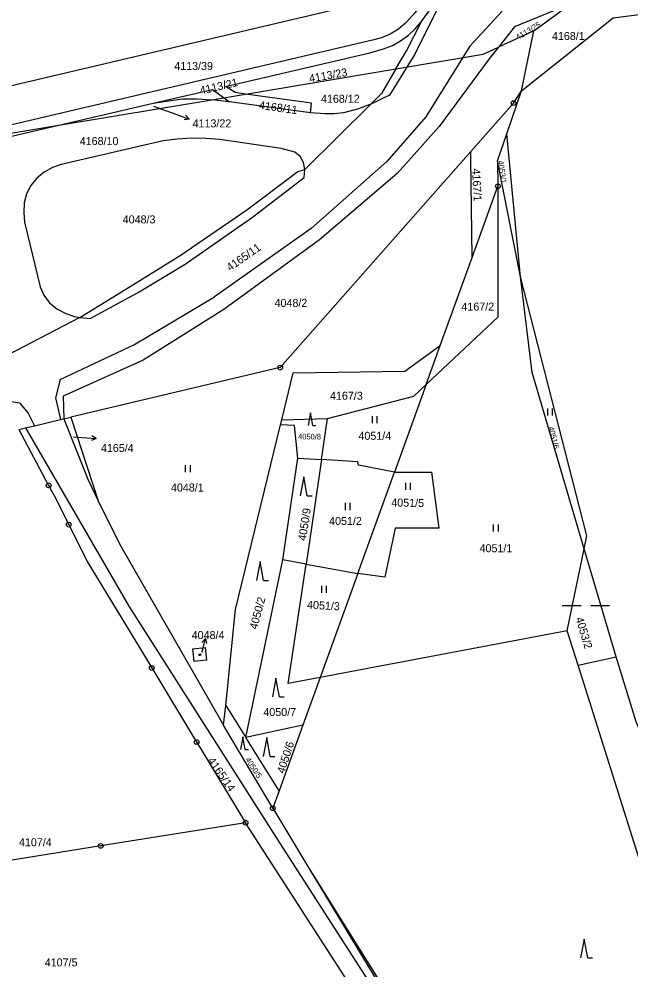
# Model space of a CAD drawing. Extents: x -733394 to -722299, y -1082822 to -1075049.
# Drawn here: x -727745.3 to -727615.3, y -1080927.6 to -1080725.9 of the extents above; entities that cross this region are included whole.
import ezdxf

# ---------------------------------------------------------------- set-up
doc = ezdxf.new("R2010")
doc.units = 0
for name, color, linetype in [('Hranice parcel', 7, 'Continuous'), ('Parcelní čísla', 7, 'Continuous'), ('Pop  PČ popisy', 7, 'Continuous'), ('Vnitřní kresba', 7, 'Continuous'), ('Značky bodu BP', 7, 'Continuous'), ('Značky budov', 7, 'Continuous'), ('Značky kultur', 7, 'Continuous')]:
    doc.layers.add(name, color=color, linetype=linetype)

msp = doc.modelspace()

# ---------------------------------------------------------------- linework, layer by layer
at = {"layer": 'Hranice parcel'}
for p, q in [((-727635.94, -1080728.37), (-727628.11, -1080722.63)), ((-727635.94, -1080728.37), (-727643.45, -1080731.86)), ((-727638.56, -1080741.16), (-727635.94, -1080728.37)), ((-727697.15, -1080741.82), (-727665.25, -1080736.48)), ((-727704.3, -1080743.02), (-727697.15, -1080741.82)), ((-727641.7, -1080750.3), (-727638.56, -1080741.16)), ((-727736.78, -1080748.45), (-727704.3, -1080743.02)), ((-727670.57, -1080743.95), (-727684.56, -1080757.87)), ((-727767.16, -1080755.55), (-727736.78, -1080748.45)), ((-727643.66, -1080756.01), (-727641.7, -1080750.3)), ((-727638.75, -1080780.61), (-727641.7, -1080750.3)), ((-727638.75, -1080780.61), (-727643.66, -1080756.01)), ((-727643.66, -1080756.01), (-727643.57, -1080761.39)), ((-727649.04, -1080776.52), (-727643.57, -1080761.39)), ((-727643.57, -1080761.39), (-727643.58, -1080789.21)), ((-727655.82, -1080795.24), (-727649.04, -1080776.52)), ((-727732.38, -1080789.25), (-727749.55, -1080798.16)), ((-727643.58, -1080789.21), (-727658.82, -1080803.52)), ((-727658.82, -1080803.52), (-727655.82, -1080795.24)), ((-727658.82, -1080803.52), (-727665.54, -1080822.1)), ((-727735.73, -1080810.78), (-727734.28, -1080810.44)), ((-727734.28, -1080810.44), (-727728.43, -1080828.19)), ((-727689.48, -1080810.99), (-727679.73, -1080810.72)), ((-727681.03, -1080819.46), (-727679.73, -1080810.72)), ((-727745.31, -1080813.05), (-727743.88, -1080812.71)), ((-727689.74, -1080812.04), (-727689.48, -1080810.99)), ((-727689.26, -1080840.74), (-727686.07, -1080819.17)), ((-727686.07, -1080819.17), (-727681.03, -1080819.46)), ((-727681.03, -1080819.46), (-727684.32, -1080841.67)), ((-727673.33, -1080843.61), (-727665.54, -1080822.1)), ((-727628.85, -1080855.79), (-727625.24, -1080838.4)), ((-727618.47, -1080861.37), (-727625.24, -1080838.4)), ((-727697.1, -1080878.47), (-727689.26, -1080840.74)), ((-727684.32, -1080841.67), (-727689.26, -1080840.74)), ((-727688.08, -1080867.01), (-727684.32, -1080841.67)), ((-727684.32, -1080841.67), (-727673.33, -1080843.61)), ((-727673.33, -1080843.61), (-727681.34, -1080865.73)), ((-727628.85, -1080855.79), (-727681.34, -1080865.73)), ((-727626.54, -1080863.13), (-727628.85, -1080855.79)), ((-727626.54, -1080863.13), (-727618.47, -1080861.37)), ((-727681.34, -1080865.73), (-727688.08, -1080867.01)), ((-727681.34, -1080865.73), (-727685, -1080875.84)), ((-727701.81, -1080875.84), (-727701.38, -1080871.67)), ((-727701.38, -1080871.67), (-727697.1, -1080878.47)), ((-727685, -1080875.84), (-727697.1, -1080878.47)), ((-727685, -1080875.84), (-727690.05, -1080889.8)), ((-727690.05, -1080889.8), (-727697.1, -1080878.47)), ((-727690.05, -1080889.8), (-727691.38, -1080893.48)), ((-727691.38, -1080893.48), (-727683.91, -1080905.87)), ((-727672.35, -1080935.05), (-727697.17, -1080896.56)), ((-727683.91, -1080905.87), (-727663.2, -1080939.07))]:
    msp.add_line(p, q, dxfattribs=at)
for points in [[(-727659.79, -1080726.38), (-727658.02, -1080723.92), (-727657.34, -1080723.65), (-727655.37, -1080716.7)], [(-727663.89, -1080719.58), (-727664.39, -1080720.63), (-727758.04, -1080742.72)], [(-727663.89, -1080719.58), (-727660.55, -1080721.71), (-727660.12, -1080722.48), (-727660.19, -1080723.19), (-727661.15, -1080724.51), (-727663.18, -1080726.75), (-727664.71, -1080728.04), (-727666.43, -1080729.13), (-727668.28, -1080729.86), (-727670.19, -1080730.39), (-727717.3, -1080741.4), (-727756.21, -1080750.58)], [(-727628.11, -1080722.63), (-727640.04, -1080727.58), (-727643.45, -1080731.86)], [(-727638.56, -1080741.16), (-727619.07, -1080725.61), (-727607.96, -1080724.23)], [(-727697.15, -1080741.82), (-727699.37, -1080741.51), (-727701.41, -1080740.19), (-727670.79, -1080733.06), (-727667.85, -1080732.24), (-727665.96, -1080731.54), (-727664.26, -1080730.55), (-727662.59, -1080729.32), (-727661.15, -1080727.95), (-727659.79, -1080726.38)], [(-727665.25, -1080736.48), (-727663, -1080732.64), (-727659.79, -1080726.38)], [(-727643.45, -1080731.86), (-727645.45, -1080734.37), (-727656.05, -1080748.73), (-727664.97, -1080758.68), (-727681.43, -1080772.76), (-727701.75, -1080787.59), (-727718.91, -1080798.33), (-727735.89, -1080805.95), (-727735.73, -1080810.78)], [(-727665.25, -1080736.48), (-727646.71, -1080733.38), (-727643.45, -1080731.86)], [(-727665.25, -1080736.48), (-727668.31, -1080741.73), (-727670.57, -1080743.95)], [(-727683.34, -1080745.79), (-727683.15, -1080743.78), (-727697.15, -1080741.82)], [(-727649.35, -1080754.05), (-727640.25, -1080743.73), (-727638.56, -1080741.16)], [(-727736.78, -1080748.45), (-727716.76, -1080743.77), (-727713.5, -1080743.25), (-727710.49, -1080742.87), (-727707.41, -1080742.81), (-727704.3, -1080743.02)], [(-727683.34, -1080745.79), (-727700.56, -1080743.45), (-727704.3, -1080743.02)], [(-727670.57, -1080743.95), (-727673.4, -1080745.06), (-727676.35, -1080745.8), (-727678.38, -1080746.02), (-727680.36, -1080746.03), (-727683.34, -1080745.79)], [(-727755.84, -1080752.15), (-727748.26, -1080750.37), (-727736.78, -1080748.45)], [(-727684.56, -1080757.87), (-727684.83, -1080756.36), (-727685.54, -1080755.08), (-727686.69, -1080754.14), (-727689.58, -1080753.37), (-727702.63, -1080751.5), (-727705.61, -1080751.26), (-727708.59, -1080751.22), (-727711.68, -1080751.37), (-727714.66, -1080751.79), (-727736.28, -1080756.75), (-727738.16, -1080757.39), (-727739.95, -1080758.4), (-727741.45, -1080759.66), (-727742.74, -1080761.26), (-727743.68, -1080762.99), (-727744.19, -1080764.91), (-727744.27, -1080766.99), (-727744.13, -1080769.02), (-727740.8, -1080782.73), (-727739.98, -1080784.56), (-727738.81, -1080786.15), (-727737.23, -1080787.42), (-727735.45, -1080788.37), (-727733.52, -1080789.07), (-727732.38, -1080789.25)], [(-727649.35, -1080754.05), (-727689.8, -1080799.92), (-727734.28, -1080810.44)], [(-727649.04, -1080776.52), (-727649.33, -1080755.52), (-727649.35, -1080754.05)], [(-727732.38, -1080789.25), (-727721.06, -1080782.31), (-727711.07, -1080776.09), (-727696.87, -1080766.4), (-727686.08, -1080758.27), (-727684.56, -1080757.87)], [(-727625.24, -1080838.4), (-727636.28, -1080800.95), (-727638.75, -1080780.61)], [(-727625.24, -1080838.4), (-727624.67, -1080835.66), (-727638.75, -1080780.61)], [(-727689.48, -1080810.99), (-727687.05, -1080801.02), (-727663.32, -1080800.66), (-727655.82, -1080795.24)], [(-727679.73, -1080810.72), (-727661.42, -1080805.96), (-727658.82, -1080803.52)], [(-727743.88, -1080812.71), (-727741.95, -1080812.26), (-727736.42, -1080810.95), (-727735.73, -1080810.78)], [(-727735.73, -1080810.78), (-727730.66, -1080823.63), (-727728.43, -1080828.19)], [(-727743.88, -1080812.71), (-727721.95, -1080850.58), (-727689.34, -1080901.82), (-727658.34, -1080950.01)], [(-727701.38, -1080871.67), (-727699.29, -1080851.32), (-727689.74, -1080812.04)], [(-727686.07, -1080819.17), (-727686.76, -1080812.22), (-727689.74, -1080812.04)], [(-727745.31, -1080813.05), (-727738.97, -1080824.92), (-727737.73, -1080827.24), (-727734.7, -1080833.27), (-727730.78, -1080841.06), (-727717.08, -1080863.71), (-727707.57, -1080879.44), (-727706.82, -1080880.67), (-727697.17, -1080896.56)], [(-727665.54, -1080822.1), (-727673.15, -1080820.64), (-727673.34, -1080819.9), (-727681.03, -1080819.46)], [(-727665.54, -1080822.1), (-727657.71, -1080822.1), (-727656.13, -1080833.98), (-727665.4, -1080833.98), (-727667.61, -1080844.4), (-727673.33, -1080843.61)], [(-727728.43, -1080828.19), (-727723.94, -1080837.35), (-727701.81, -1080875.84)], [(-727708.08, -1080862.3), (-727708.36, -1080859.67), (-727705.71, -1080859.35), (-727705.44, -1080862.02), (-727708.08, -1080862.3)], [(-727574.67, -1080916.7), (-727610.98, -1080912.54), (-727626.54, -1080863.13)], [(-727574.67, -1080916.7), (-727602.88, -1080902.31), (-727614.23, -1080875.16), (-727618.47, -1080861.37)], [(-727691.38, -1080893.48), (-727700.2, -1080878.64), (-727701.81, -1080875.84)], [(-727697.17, -1080896.56), (-727727.92, -1080901.5), (-727782.38, -1080910.26)], [(-727683.91, -1080905.87), (-727668.25, -1080931.84), (-727663.2, -1080939.07)]]:
    msp.add_lwpolyline(points, dxfattribs=at)
at = {"layer": 'Pop  PČ popisy'}
for p, q in [((-727716.68, -1080744.41), (-727711.93, -1080746.12)), ((-727711.93, -1080746.12), (-727709.11, -1080747.15)), ((-727709.11, -1080747.15), (-727710.22, -1080747.27)), ((-727709.11, -1080747.15), (-727709.88, -1080746.33)), ((-727733.69, -1080814.65), (-727731.86, -1080814.79)), ((-727731.86, -1080814.79), (-727728.87, -1080815)), ((-727728.87, -1080815), (-727729.83, -1080814.43)), ((-727728.87, -1080815), (-727729.9, -1080815.43)), ((-727705.7, -1080857.43), (-727706.41, -1080858.29)), ((-727706.37, -1080860.35), (-727705.7, -1080857.43)), ((-727705.7, -1080857.43), (-727705.43, -1080858.51)), ((-727706.38, -1080860.39), (-727706.37, -1080860.35))]:
    msp.add_line(p, q, dxfattribs=at)
at = {"layer": 'Vnitřní kresba'}
for p, q in [((-727656.6, -1080724.06), (-727661.2, -1080733.33)), ((-727649.53, -1080731.62), (-727642.7, -1080724.2)), ((-727649.53, -1080731.62), (-727658.89, -1080746.63)), ((-727661.2, -1080733.33), (-727666.59, -1080742.06)), ((-727716.76, -1080743.77), (-727704.16, -1080740.85)), ((-727704.16, -1080740.85), (-727700.56, -1080743.45)), ((-727666.59, -1080742.06), (-727670.57, -1080743.95)), ((-727658.89, -1080746.63), (-727667.16, -1080756.17)), ((-727667.16, -1080756.17), (-727683.25, -1080770.39)), ((-727684.72, -1080759.52), (-727684.56, -1080757.87)), ((-727695.66, -1080767.99), (-727684.72, -1080759.52)), ((-727710, -1080777.93), (-727695.66, -1080767.99)), ((-727683.25, -1080770.39), (-727703.74, -1080784.92)), ((-727720.09, -1080784.02), (-727710, -1080777.93)), ((-727730.15, -1080789.48), (-727720.09, -1080784.02)), ((-727720.9, -1080795.07), (-727703.74, -1080784.92)), ((-727732.38, -1080789.25), (-727730.15, -1080789.48)), ((-727736.52, -1080802.47), (-727720.9, -1080795.07)), ((-727736.52, -1080802.47), (-727737.48, -1080806.37)), ((-727737.48, -1080806.37), (-727736.42, -1080810.95)), ((-727747.62, -1080806.94), (-727745.17, -1080807.41)), ((-727745.17, -1080807.41), (-727743.31, -1080809.6)), ((-727743.31, -1080809.6), (-727741.95, -1080812.26))]:
    msp.add_line(p, q, dxfattribs=at)
at = {"layer": 'Značky bodu BP'}
for centre, radius in [((-727640.25, -1080743.73), 0.5), ((-727640.25, -1080743.73), 0.0303), ((-727643.57, -1080761.39), 0.5), ((-727643.57, -1080761.39), 0.0303), ((-727689.8, -1080799.92), 0.5), ((-727689.8, -1080799.92), 0.0303), ((-727738.97, -1080824.92), 0.5), ((-727738.97, -1080824.92), 0.0303), ((-727734.7, -1080833.27), 0.5), ((-727734.7, -1080833.27), 0.0303), ((-727717.08, -1080863.71), 0.5), ((-727717.08, -1080863.71), 0.0303), ((-727707.57, -1080879.44), 0.5), ((-727707.57, -1080879.44), 0.0303), ((-727691.38, -1080893.48), 0.5), ((-727691.38, -1080893.48), 0.0303), ((-727697.17, -1080896.56), 0.5), ((-727697.17, -1080896.56), 0.0303), ((-727727.92, -1080901.5), 0.5), ((-727727.92, -1080901.5), 0.0303)]:
    msp.add_circle(centre, radius, dxfattribs=at)
at = {"layer": 'Značky budov'}
msp.add_circle((-727706.86, -1080860.91), 0.175, dxfattribs=at)
at = {"layer": 'Značky kultur'}
for p, q in [((-727632.98, -1080810.11), (-727632.98, -1080808.61)), ((-727631.98, -1080810.11), (-727631.98, -1080808.61)), ((-727683.4, -1080809.52), (-727683.9, -1080812.2)), ((-727682.9, -1080812.2), (-727683.4, -1080809.52)), ((-727670.21, -1080811.7), (-727670.21, -1080810.2)), ((-727669.21, -1080811.7), (-727669.21, -1080810.2)), ((-727682.9, -1080812.2), (-727682.23, -1080812.2)), ((-727709.88, -1080822.13), (-727709.88, -1080820.63)), ((-727708.88, -1080822.13), (-727708.88, -1080820.63)), ((-727684.8, -1080823.12), (-727685.55, -1080827.12)), ((-727684.05, -1080827.12), (-727684.8, -1080823.12)), ((-727663.16, -1080825.9), (-727663.16, -1080824.4)), ((-727662.16, -1080825.9), (-727662.16, -1080824.4)), ((-727684.05, -1080827.12), (-727683.05, -1080827.12)), ((-727675.92, -1080830.16), (-727675.92, -1080828.66)), ((-727674.92, -1080830.16), (-727674.92, -1080828.66)), ((-727644.48, -1080834.75), (-727644.48, -1080833.25)), ((-727643.48, -1080834.75), (-727643.48, -1080833.25)), ((-727694.07, -1080841.11), (-727694.82, -1080845.11)), ((-727693.32, -1080845.11), (-727694.07, -1080841.11)), ((-727693.32, -1080845.11), (-727692.32, -1080845.11)), ((-727680.94, -1080847.73), (-727680.94, -1080846.23)), ((-727679.94, -1080847.73), (-727679.94, -1080846.23)), ((-727629.9, -1080850.47), (-727625.88, -1080850.47)), ((-727623.87, -1080850.47), (-727619.85, -1080850.47)), ((-727690.72, -1080865.85), (-727691.47, -1080869.85)), ((-727689.97, -1080869.85), (-727690.72, -1080865.85)), ((-727689.97, -1080869.85), (-727688.97, -1080869.85)), ((-727697.71, -1080878.35), (-727698.21, -1080881.03)), ((-727697.21, -1080881.03), (-727697.71, -1080878.35)), ((-727692.66, -1080878.5), (-727693.41, -1080882.5)), ((-727691.91, -1080882.5), (-727692.66, -1080878.5)), ((-727697.21, -1080881.03), (-727696.54, -1080881.03)), ((-727691.91, -1080882.5), (-727690.91, -1080882.5)), ((-727625.26, -1080921.27), (-727626.01, -1080925.27)), ((-727624.51, -1080925.27), (-727625.26, -1080921.27)), ((-727624.51, -1080925.27), (-727623.51, -1080925.27))]:
    msp.add_line(p, q, dxfattribs=at)

# ---------------------------------------------------------------- texts
at = {"layer": 'Parcelní čísla'}
for s, height, rotation, p in [('4113/25', 1.19, 31, (-727639.29, -1080730.37)), ('4113/23', 1.7, 10, (-727683.52, -1080739.39)), ('4113/21', 1.7, 13, (-727706.67, -1080741.93)), ('4168/11', 1.7, 352, (-727694.39, -1080744.96)), ('4053/1', 1.19, 278, (-727643.57, -1080756.02)), ('4167/1', 1.7, 273, (-727649.07, -1080757.67)), ('4165/11', 1.7, 35, (-727700.46, -1080779.51)), ('4051/6', 1.19, 285, (-727632.9, -1080812.59)), ('4051/5', 1.7, 359, (-727666.23, -1080829.41)), ('4050/9', 1.7, 81, (-727684.36, -1080836.77)), ('4050/2', 1.7, 75, (-727694.72, -1080855.64)), ('4051/3', 1.7, 357, (-727684.14, -1080851.11)), ('4053/2', 1.7, 287, (-727627.12, -1080853.16)), ('4050/6', 1.7, 72, (-727688.95, -1080886.25)), ('4165/14', 1.7, 305, (-727705.3, -1080883.41)), ('4050/5', 1.19, 303, (-727697.26, -1080883.18))]:
    msp.add_text(s, height=height, rotation=rotation, dxfattribs=at).set_placement(p)
for s, height, p in [('4168/1', 1.7, (-727632.1, -1080730.34)), ('4113/39', 1.7, (-727712.3, -1080736.72)), ('4168/12', 1.7, (-727681.15, -1080743.68)), ('4113/22', 1.7, (-727708.41, -1080748.9)), ('4168/10', 1.7, (-727732.37, -1080752.66)), ('4048/3', 1.7, (-727723.24, -1080769.29)), ('4048/2', 1.7, (-727691, -1080787.03)), ('4167/2', 1.7, (-727651.33, -1080787.81)), ('4167/3', 1.7, (-727679.23, -1080806.74)), ('4050/8', 1.19, (-727686.01, -1080815.17)), ('4051/4', 1.7, (-727673.19, -1080815.25)), ('4165/4', 1.7, (-727727.87, -1080817.84)), ('4048/1', 1.7, (-727713, -1080826.23)), ('4051/2', 1.7, (-727679.42, -1080833.34)), ('4051/1', 1.7, (-727647.47, -1080839.13)), ('4048/4', 1.7, (-727708.6, -1080857.56)), ('4050/7', 1.7, (-727693.38, -1080873.91)), ('4107/4', 1.7, (-727745.27, -1080901.57)), ('4107/5', 1.7, (-727739.8, -1080927.08))]:
    msp.add_text(s, height=height, dxfattribs=at).set_placement(p)

doc.saveas('drawing.dxf')
